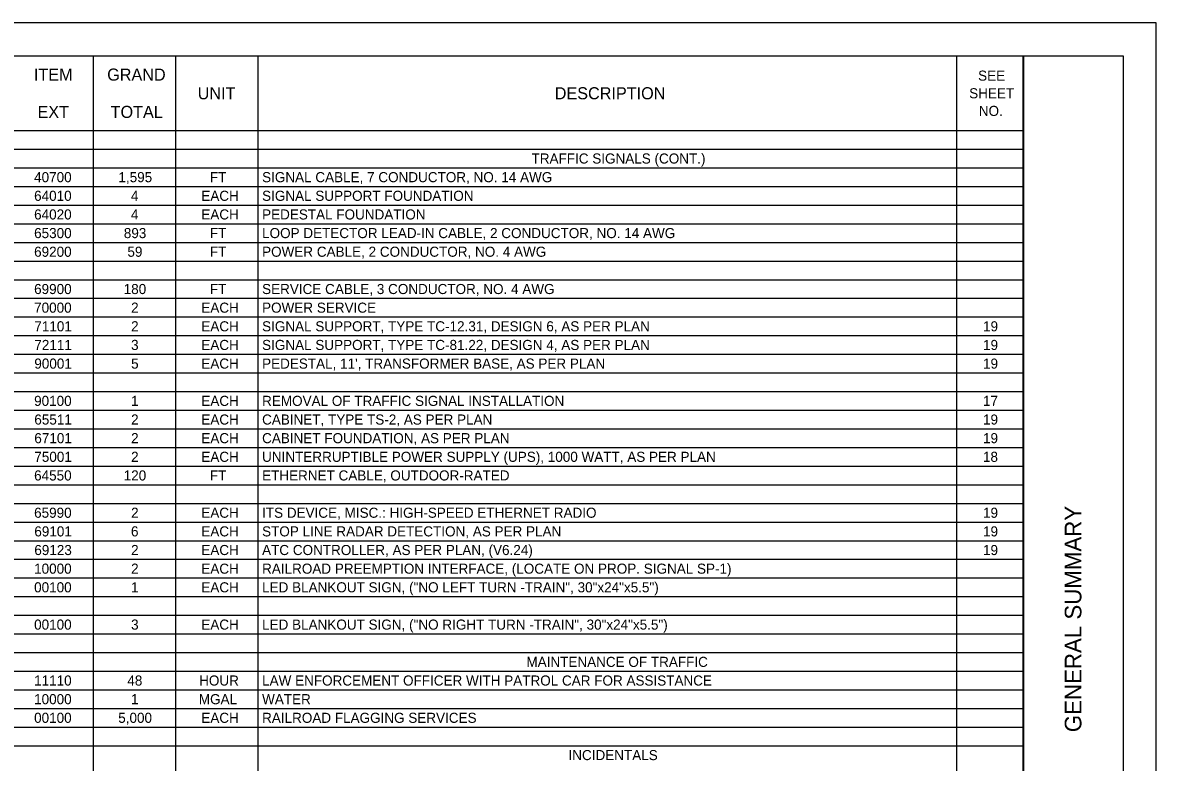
# Model space of a CAD drawing. Extents: x 0 to 34, y 0 to 22.
# Drawn here: x 16.98 to 34, y 10.89 to 22 of the extents above; entities that cross this region are included whole.
import ezdxf

# ---------------------------------------------------------------- set-up
doc = ezdxf.new("R2010")
doc.units = 0
for name, color, linetype in [('SH_Border', 7, 'Continuous'), ('SH_Cut_Line', 7, 'Continuous'), ('SH_Data', 7, 'Continuous'), ('SH_Text', 7, 'Continuous')]:
    doc.layers.add(name, color=color, linetype=linetype)

msp = doc.modelspace()

# ---------------------------------------------------------------- linework, layer by layer
at = {"layer": 'SH_Border'}
msp.add_line((32, 0.5), (32, 21.5), dxfattribs=at)
msp.add_lwpolyline([(1.5, 21.5), (33.5, 21.5), (33.5, 0.5), (1.5, 0.5)], close=True, dxfattribs=at)
at = {"layer": 'SH_Cut_Line'}
msp.add_lwpolyline([(0, 0), (34, 0), (34, 22), (0, 22)], close=True, dxfattribs=at)
at = {"layer": 'SH_Text'}
for p, q in [((1.5, 21.5), (32.004, 21.5)), ((18.036, 21.5), (18.036, 0.5)), ((19.272, 21.5), (19.272, 0.5)), ((20.507, 21.5), (20.507, 0.5)), ((30.999, 21.5), (30.999, 0.5)), ((32.004, 21.5), (32.004, 0.5)), ((1.5, 20.38), (32.004, 20.38)), ((1.5, 20.1), (32.004, 20.1)), ((1.5, 19.82), (32.004, 19.82)), ((1.5, 19.54), (32.004, 19.54)), ((1.5, 19.26), (32.004, 19.26)), ((1.5, 18.98), (32.004, 18.98)), ((1.5, 18.7), (32.004, 18.7)), ((1.5, 18.42), (32.004, 18.42)), ((1.5, 18.14), (32.004, 18.14)), ((1.5, 17.86), (32.004, 17.86)), ((1.5, 17.58), (32.004, 17.58)), ((1.5, 17.3), (32.004, 17.3)), ((1.5, 17.02), (32.004, 17.02)), ((1.5, 16.74), (32.004, 16.74)), ((1.5, 16.46), (32.004, 16.46)), ((1.5, 16.18), (32.004, 16.18)), ((1.5, 15.9), (32.004, 15.9)), ((1.5, 15.62), (32.004, 15.62)), ((1.5, 15.34), (32.004, 15.34)), ((1.5, 15.06), (32.004, 15.06)), ((1.5, 14.78), (32.004, 14.78)), ((1.5, 14.5), (32.004, 14.5)), ((1.5, 14.22), (32.004, 14.22)), ((1.5, 13.94), (32.004, 13.94)), ((1.5, 13.66), (32.004, 13.66)), ((1.5, 13.38), (32.004, 13.38)), ((1.5, 13.1), (32.004, 13.1)), ((1.5, 12.82), (32.004, 12.82)), ((1.5, 12.54), (32.004, 12.54)), ((1.5, 12.26), (32.004, 12.26)), ((1.5, 11.98), (32.004, 11.98)), ((1.5, 11.7), (32.004, 11.7)), ((1.5, 11.42), (32.004, 11.42)), ((1.5, 11.14), (32.004, 11.14))]:
    msp.add_line(p, q, dxfattribs=at)

# ---------------------------------------------------------------- texts
at = {"layer": 'SH_Data'}
msp.add_text('GENERAL SUMMARY', height=0.25, rotation=90, dxfattribs=at).set_placement((32.875, 11.344))
at = {"layer": 'SH_Text'}
for s, height, p in [('ITEM', 0.1818, (17.147, 21.129)), ('GRAND', 0.1818, (18.247, 21.129)), ('SEE ', 0.1515, (31.324, 21.129)), ('UNIT', 0.1818, (19.606, 20.849)), ('DESCRIPTION', 0.18184, (24.967, 20.849)), ('SHEET ', 0.1515, (31.19, 20.864)), ('EXT', 0.1818, (17.201, 20.569)), ('TOTAL', 0.1818, (18.299, 20.569)), ('NO.', 0.1515, (31.335, 20.599)), ('TRAFFIC SIGNALS (CONT.)', 0.15153, (24.619, 19.884)), ('40700', 0.1515, (17.15, 19.604)), ('1,595', 0.1515, (18.416, 19.604)), ('FT', 0.1515, (19.789, 19.604)), ('SIGNAL CABLE, 7 CONDUCTOR, NO. 14 AWG', 0.15153, (20.573, 19.604)), ('64010', 0.1515, (17.15, 19.324)), ('4', 0.152, (18.603, 19.324)), ('EACH', 0.1515, (19.661, 19.324)), ('SIGNAL SUPPORT FOUNDATION', 0.15153, (20.573, 19.324)), ('64020', 0.1515, (17.15, 19.044)), ('4', 0.152, (18.603, 19.044)), ('EACH', 0.1515, (19.661, 19.044)), ('PEDESTAL FOUNDATION', 0.15153, (20.573, 19.044)), ('65300', 0.1515, (17.15, 18.764)), ('893', 0.1515, (18.497, 18.764)), ('FT', 0.1515, (19.789, 18.764)), ('LOOP DETECTOR LEAD-IN CABLE, 2 CONDUCTOR, NO. 14 AWG', 0.15153, (20.573, 18.764)), ('69200', 0.1515, (17.15, 18.484)), ('59', 0.1515, (18.551, 18.484)), ('FT', 0.1515, (19.789, 18.484)), ('POWER CABLE, 2 CONDUCTOR, NO. 4 AWG', 0.15153, (20.573, 18.484)), ('69900', 0.1515, (17.15, 17.924)), ('180', 0.1515, (18.495, 17.924)), ('FT', 0.1515, (19.789, 17.924)), ('SERVICE CABLE, 3 CONDUCTOR, NO. 4 AWG', 0.15153, (20.573, 17.924)), ('70000', 0.1515, (17.15, 17.644)), ('2', 0.152, (18.606, 17.644)), ('EACH', 0.1515, (19.661, 17.644)), ('POWER SERVICE', 0.15153, (20.573, 17.644)), ('71101', 0.1515, (17.153, 17.364)), ('2', 0.152, (18.606, 17.364)), ('EACH', 0.1515, (19.661, 17.364)), ('SIGNAL SUPPORT, TYPE TC-12.31, DESIGN 6, AS PER PLAN', 0.15153, (20.573, 17.364)), ('19', 0.1515, (31.398, 17.364)), ('72111', 0.1515, (17.153, 17.084)), ('3', 0.152, (18.606, 17.084)), ('EACH', 0.1515, (19.661, 17.084)), ('SIGNAL SUPPORT, TYPE TC-81.22, DESIGN 4, AS PER PLAN', 0.15153, (20.573, 17.084)), ('19', 0.1515, (31.398, 17.084)), ('90001', 0.1515, (17.153, 16.804)), ('5', 0.152, (18.606, 16.804)), ('EACH', 0.1515, (19.661, 16.804)), ("PEDESTAL, 11', TRANSFORMER BASE, AS PER PLAN", 0.15153, (20.573, 16.804)), ('19', 0.1515, (31.398, 16.804)), ('90100', 0.1515, (17.15, 16.244)), ('1', 0.152, (18.606, 16.244)), ('EACH', 0.1515, (19.661, 16.244)), ('REMOVAL OF TRAFFIC SIGNAL INSTALLATION', 0.15153, (20.573, 16.244)), ('17', 0.1515, (31.397, 16.244)), ('65511', 0.1515, (17.153, 15.964)), ('2', 0.152, (18.606, 15.964)), ('EACH', 0.1515, (19.661, 15.964)), ('CABINET, TYPE TS-2, AS PER PLAN', 0.15153, (20.573, 15.964)), ('19', 0.1515, (31.398, 15.964)), ('67101', 0.1515, (17.153, 15.684)), ('2', 0.152, (18.606, 15.684)), ('EACH', 0.1515, (19.661, 15.684)), ('CABINET FOUNDATION, AS PER PLAN', 0.15153, (20.573, 15.684)), ('19', 0.1515, (31.398, 15.684)), ('75001', 0.1515, (17.153, 15.404)), ('2', 0.152, (18.606, 15.404)), ('EACH', 0.1515, (19.661, 15.404)), ('UNINTERRUPTIBLE POWER SUPPLY (UPS), 1000 WATT, AS PER PLAN', 0.15153, (20.573, 15.404)), ('18', 0.1515, (31.397, 15.404)), ('64550', 0.1515, (17.15, 15.124)), ('120', 0.1515, (18.495, 15.124)), ('FT', 0.1515, (19.789, 15.124)), ('ETHERNET CABLE, OUTDOOR-RATED', 0.15153, (20.573, 15.124)), ('65990', 0.1515, (17.15, 14.564)), ('2', 0.152, (18.606, 14.564)), ('EACH', 0.1515, (19.661, 14.564)), ('ITS DEVICE, MISC.: HIGH-SPEED ETHERNET RADIO', 0.15153, (20.573, 14.564)), ('19', 0.1515, (31.398, 14.564)), ('69101', 0.1515, (17.153, 14.284)), ('6', 0.152, (18.604, 14.284)), ('EACH', 0.1515, (19.661, 14.284)), ('STOP LINE RADAR DETECTION, AS PER PLAN', 0.15153, (20.573, 14.284)), ('19', 0.1515, (31.398, 14.284)), ('69123', 0.1515, (17.153, 14.004)), ('2', 0.152, (18.606, 14.004)), ('EACH', 0.1515, (19.661, 14.004)), ('ATC CONTROLLER, AS PER PLAN, (V6.24)', 0.15153, (20.573, 14.004)), ('19', 0.1515, (31.398, 14.004)), ('10000', 0.1515, (17.15, 13.724)), ('2', 0.152, (18.606, 13.724)), ('EACH', 0.1515, (19.661, 13.724)), ('RAILROAD PREEMPTION INTERFACE, (LOCATE ON PROP. SIGNAL SP-1)', 0.15153, (20.573, 13.724)), ('00100', 0.1515, (17.15, 13.444)), ('1', 0.152, (18.606, 13.444)), ('EACH', 0.1515, (19.661, 13.444)), ('LED BLANKOUT SIGN, ("NO LEFT TURN -TRAIN", 30"x24"x5.5")', 0.15153, (20.573, 13.444)), ('00100', 0.1515, (17.15, 12.884)), ('3', 0.152, (18.606, 12.884)), ('EACH', 0.1515, (19.661, 12.884)), ('LED BLANKOUT SIGN, ("NO RIGHT TURN -TRAIN", 30"x24"x5.5")', 0.15153, (20.573, 12.884)), ('MAINTENANCE OF TRAFFIC', 0.15153, (24.542, 12.324)), ('11110', 0.1515, (17.15, 12.044)), ('48', 0.1515, (18.55, 12.044)), ('HOUR', 0.1515, (19.628, 12.044)), ('LAW ENFORCEMENT OFFICER WITH PATROL CAR FOR ASSISTANCE', 0.15153, (20.573, 12.044)), ('10000', 0.1515, (17.15, 11.764)), ('1', 0.152, (18.606, 11.764)), ('MGAL', 0.1515, (19.623, 11.764)), ('WATER', 0.1515, (20.573, 11.764)), ('00100', 0.1515, (17.15, 11.484)), ('5,000', 0.1515, (18.413, 11.484)), ('EACH', 0.1515, (19.661, 11.484)), ('RAILROAD FLAGGING SERVICES', 0.15153, (20.573, 11.484)), ('INCIDENTALS', 0.15153, (25.174, 10.924))]:
    msp.add_text(s, height=height, dxfattribs=at).set_placement(p)

doc.saveas('drawing.dxf')
